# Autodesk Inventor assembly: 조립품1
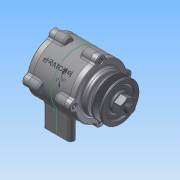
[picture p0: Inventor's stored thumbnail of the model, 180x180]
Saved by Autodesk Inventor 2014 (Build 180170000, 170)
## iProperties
Created: 2015-03
Part Number: 조립품1
Document SubType Name: Assembly
Designer: net
Author: net
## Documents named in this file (11)
- C:\Users\net\Documents\Inventor\450305V1054\조립품1.iam
- C:\Users\net\Documents\Inventor\450305V1054\본체.ipt
- C:\Users\net\Desktop\450305V1054\커버.ipt
- C:\Users\net\Desktop\450305V1054\커버2.ipt
- C:\Users\net\Desktop\450305V1054\베어링 6204.ipt
- C:\Users\net\Desktop\450305V1054\축.ipt
- C:\Users\net\Desktop\450305V1054\오일실.ipt
- C:\Users\net\Desktop\450305V1054\키(4 x 4 x 12).ipt
- C:\Users\net\Desktop\450305V1054\V벨트풀리.ipt
- C:\Users\net\Desktop\450305V1054\M 4 x 12.ipt
- C:\Users\net\Desktop\450305V1054\너트 M12x1.25.ipt
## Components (14 placed, 6 different names)
1. KS B 2023 6204 - 20 x 47 x 14:1
2. KS B 2023 6204 - 20 x 47 x 14:2
3. KS B 2804 D D - 20 32 8:1
4. KS B 1311 (I) 4 x 4 x 12:1 — 각도:1, 각도:2
5. 그루브 풀리1:1 — 각도:2
6. KS B 1012 클래스 1 일반 - 미터 M12x1.25:1
7. KS B 1003 - 미터 M 4 x 12:2
8. KS B 1003 - 미터 M 4 x 12:3
9. KS B 1003 - 미터 M 4 x 12:4
10. KS B 1003 - 미터 M 4 x 12:5
11. KS B 1003 - 미터 M 4 x 12:1
12. KS B 1003 - 미터 M 4 x 12:6
13. KS B 1003 - 미터 M 4 x 12:7
14. KS B 1003 - 미터 M 4 x 12:8
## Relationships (2: Angle 2)
- 각도:1 [Angle]: KS B 1311 (I) 4 x 4 x 12:1
- 각도:2 [Angle]: KS B 1311 (I) 4 x 4 x 12:1 ↔ 그루브 풀리1:1
